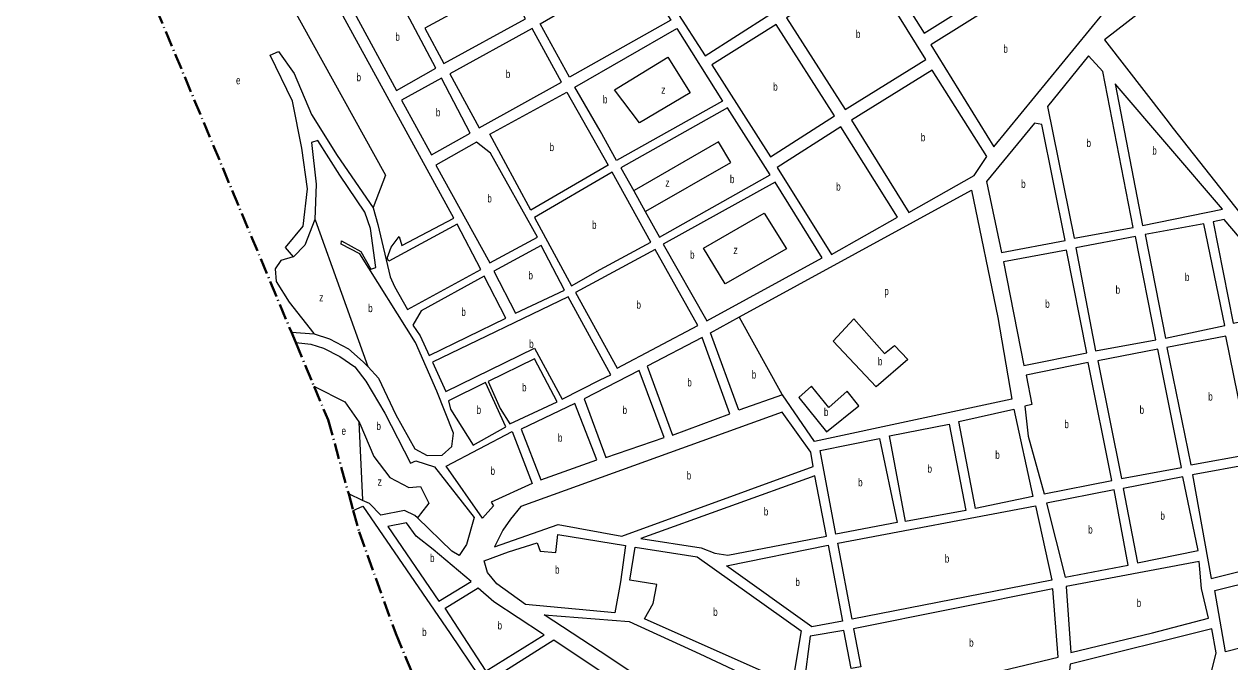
# Model space of a CAD drawing. Extents: x 639657 to 671642, y 222838 to 252123.
# Drawn here: x 641280 to 642787, y 245964 to 246761 of the extents above; entities that cross this region are included whole.
import ezdxf

# ---------------------------------------------------------------- set-up
doc = ezdxf.new("R2010")
doc.units = 0
doc.header["$LTSCALE"] = 4
doc.linetypes.add('DOT_DASHED', pattern=[7.7, 5, -1.2, 0.3, -1.2])
for name, color, linetype, lineweight in [('1', 7, 'Continuous', 13), ('21', 7, 'Continuous', 13), ('4', 7, 'DOT_DASHED', 40)]:
    doc.layers.add(name, color=color, linetype=linetype, lineweight=lineweight)
doc.layers.add('7', color=7, linetype='Continuous')

msp = doc.modelspace()

# ---------------------------------------------------------------- linework, layer by layer
at = {"layer": '1'}
msp.add_line((641614.514, 246376.116), (641643.04, 246373.95), dxfattribs=at)
for points in [[(641716.6, 246531.44), (641722.63, 246510.59), (641737.7, 246445.46), (641743.08, 246433.43), (641759.42, 246404.64), (641851.3, 246454.43), (641821.42, 246511.15), (641736.19, 246465.03), (641734.25, 246468.68), (641738.97, 246482.23), (641749.06, 246495.79), (641752.5, 246484.62), (641817.33, 246518.45), (641674.33, 246779.45), (641657.56, 246797.05), (641633.48, 246825.18), (641505.46, 247072.14), (641435.84, 247093.75)], [(642718.85, 246809.55), (642706.38, 246800.73), (642630.47, 246741.39), (642707.2, 246642.72), (642716.44, 246630.68)], [(641616.99, 246470.46), (641607.1, 246482.06), (641628.99, 246508.54), (641634.54, 246555.41), (641627.64, 246606.14), (641615.78, 246665.02), (641588.03, 246722.17), (641598.12, 246726.69), (641617.69, 246699.42), (641639.63, 246648.29), (641671.67, 246596.95), (641716.6, 246531.44)], [(642159.18, 246656.56), (642026.29, 246581.68), (642042.227, 246552.992), (642056.659, 246527.011)], [(642056.659, 246527.011), (642074.42, 246495.04), (642212.48, 246572.93), (642159.18, 246656.56)], [(642716.44, 246630.68), (642819.58, 246499.75), (642895.27, 246558.24), (642908.698, 246569.102)], [(641710.176, 246332.895), (641723.39, 246318.79), (641745.11, 246272.8), (641768.75, 246230.46), (641784.22, 246222.09), (641802.69, 246222.55), (641814.71, 246233.32), (641817.06, 246250.1), (641796.2, 246302.54), (641769.32, 246363.37), (641700.1, 246474.23), (641676.69, 246486.24), (641676.9, 246490.11), (641701.39, 246477.02), (641713.86, 246454.89), (641720.09, 246457.05), (641713.4, 246505.85), (641706.08, 246526.26), (641674.91, 246572.23), (641647.39, 246615.84), (641639.66, 246613.03), (641645.28, 246561.01), (641643.81, 246516.94)], [(642174.226, 246395.165), (642464.24, 246553.65), (642497.07, 246394.32), (642514.87, 246292.6), (642268.04, 246239.4), (642228.07, 246297.89), (642173.45, 246278.52)], [(641643.81, 246516.94), (641631.37, 246484.89), (641616.99, 246470.46)], [(642173.45, 246278.52), (642138.24, 246375.5), (642174.226, 246395.165)], [(641643.04, 246373.95), (641661.94, 246367.96), (641685.79, 246355.3), (641704.27, 246339.2), (641710.176, 246332.895)], [(641619.913, 246363.208), (641638.75, 246361.26), (641654.65, 246356.12), (641675.06, 246345.61), (641693.53, 246332.95), (641707.5, 246314.9), (641731.15, 246275.15), (641763.18, 246212.39), (641769.84, 246215.19), (641793.11, 246207.97), (641842.67, 246144.74), (641833.24, 246110.75), (641824.01, 246097.18), (641814.77, 246102.33), (641772.009, 246144.096)], [(641772.009, 246144.096), (641768.8, 246147.23), (641755.91, 246153.23), (641726.07, 246147.39), (641711.88, 246162), (641703.438, 246165.969), (641686.028, 246174.155)], [(641691.823, 246153.325), (641703.51, 246158.76), (641812.89, 245999.72), (641848.25, 245947.02), (641785.16, 245905.85), (641790.17, 245895.57)]]:
    msp.add_lwpolyline(points, dxfattribs=at)
for points in [[(642392.94, 246943.2), (642282, 246945.54), (642404.95, 246749.94), (642483.86, 246799.4)], [(642212.1, 246773.11), (642141.59, 246883.8), (642057.51, 246836.9), (642131.46, 246721.69)], [(642628.76, 246774.28), (642585.13, 246842.85), (642413.55, 246735.11), (642492.2, 246607.84)], [(642088.68, 246766.18), (641962.09, 246694.63), (641925.31, 246761.42), (641999.59, 246804.74), (642047.41, 246831.1)], [(642407.09, 246717.05), (642335.09, 246833.12), (642232.95, 246769.03), (642306.46, 246654.45)], [(641882.75, 246811.45), (641781.2, 246756.06), (641804.86, 246712.03), (641906.84, 246767.85)], [(641794.87, 246706.1), (641743.9, 246802.33), (641692.8, 246775.61), (641745.71, 246678.31)], [(641848.95, 246631.69), (641952, 246688.59), (641915.22, 246755.82), (641812.6, 246699.14)], [(642000.15, 246627.82), (641968.74, 246682.25), (642095.99, 246755.44), (642153.16, 246664.94), (642020.7, 246590.71)], [(642292.91, 246646.49), (642220.05, 246760.64), (642139.63, 246710.09), (642212.92, 246595.29)], [(642666.31, 246506.82), (642628.32, 246701.83), (642610.48, 246721.39), (642559.08, 246658.17), (642592.35, 246493.69)], [(641837.67, 246624.9), (641801.97, 246693.64), (641751.95, 246666.06), (641789.36, 246597.96)], [(642483.39, 246595.8), (642415.05, 246703.72), (642314.2, 246640.91), (642385.76, 246525.68), (642467.47, 246572.15)], [(641958.45, 246676.13), (642010.38, 246584.9), (641913.46, 246528.8), (641862.49, 246623.54)], [(642778.1, 246530.06), (642643.58, 246686.57), (642677.92, 246509.62)], [(642371.78, 246520.08), (642300.86, 246632.95), (642221.3, 246581.97), (642289.2, 246473.18)], [(642581.17, 246490.89), (642551.98, 246635.81), (642543.16, 246637.31), (642482.95, 246564.62), (642501.83, 246475.61)], [(641922.15, 246494.94), (641863.24, 246600), (641845.62, 246613.73), (641794.96, 246584.86), (641862.47, 246462.83)], [(641964.48, 246434.15), (642000.12, 246454.63), (642063.45, 246488.8), (642015.13, 246576.3), (641918.05, 246519.66)], [(642277.59, 246469.09), (642218.93, 246563.69), (642079.15, 246486.01), (642133.51, 246390.33)], [(642780.84, 246384.48), (642754.45, 246511.35), (642681.14, 246498.22), (642706.67, 246368.77)], [(642875.65, 246404.5), (642780.03, 246516.94), (642766.06, 246514.15), (642791.16, 246387.28)], [(642669.1, 246495.64), (642594.71, 246481.65), (642619.16, 246352.84), (642694.41, 246366.41)], [(641926.45, 246484.42), (641867.41, 246452.3), (641894.5, 246399.87), (641955.68, 246428.77)], [(641969.64, 246425.77), (642021.47, 246331.36), (642122.33, 246384.31), (642069.04, 246479.56)], [(642583.1, 246478.85), (642504.19, 246464), (642529.72, 246334.33), (642608.2, 246350.26)], [(641882.26, 246393.62), (641855.39, 246446.05), (641776.6, 246402.94), (641766.3, 246385.08), (641775.33, 246371.76), (641786.73, 246347.05)], [(641952.96, 246292.64), (642000.19, 246316.79), (642013.72, 246322.97), (641960.41, 246420.39), (641790.6, 246338.66), (641807.37, 246302.13), (641918.14, 246356.04)], [(642127.91, 246369.47), (642059.1, 246333.74), (642090.66, 246247.3), (642162.27, 246274.21)], [(642781.91, 246371.15), (642708.38, 246357.16), (642738.19, 246210.28), (642811.93, 246223.84)], [(642697.2, 246354.79), (642621.95, 246340.37), (642651.76, 246193.49), (642726.58, 246207.05)], [(641887.49, 246261.8), (641946.52, 246289.19), (641918.15, 246342.7), (641860.19, 246314.67), (641875.45, 246280.71)], [(642609.91, 246338.43), (642532.51, 246322.29), (642539.81, 246285.94), (642530.99, 246283.57), (642535.27, 246246.15), (642555.01, 246174.11), (642639.72, 246190.9)], [(641980.23, 246292.68), (642007.44, 246219.73), (642080.34, 246244.5), (642048.99, 246328.15)], [(641882.34, 246257.71), (641856.97, 246313.38), (641810.6, 246290.52), (641813.39, 246279.77), (641841.55, 246234.86)], [(641996.16, 246216.78), (641968.64, 246286.86), (641901.45, 246254.94), (641926.17, 246191.74)], [(641947.89, 246135.85), (642027.28, 246121.41), (642266.3, 246208.22), (642263.51, 246226.07), (642227.63, 246276.17), (641900.97, 246158.16), (641888.19, 246142.44), (641878.75, 246128.87), (641868.24, 246107.99)], [(642469.22, 246155.8), (642448.43, 246264.63), (642517.01, 246279.91), (642540.82, 246170.88)], [(642381.93, 246139.64), (642361.99, 246246.53), (642436.17, 246261.4), (642457.18, 246153.22)], [(641853.19, 246143.68), (641807.85, 246208.7), (641890.28, 246252.13), (641915.44, 246187), (641863.92, 246163.7), (641867.14, 246158.97)], [(642294.63, 246123.7), (642275.12, 246228.22), (642349.31, 246243.3), (642371.18, 246138.13)], [(642837, 246086.62), (642813.43, 246211.15), (642740.33, 246197.81), (642763.69, 246068.54)], [(642283.02, 246121.33), (642268.66, 246196.6), (642051.25, 246118.22), (642126.28, 246106.85), (642143.48, 246099.98), (642159.82, 246097.62)], [(642747.37, 246103.38), (642728.29, 246195.44), (642653.69, 246181.01), (642671.69, 246088.1)], [(642660.08, 246084.87), (642642.51, 246179.07), (642557.8, 246162.49), (642581.39, 246070.01)], [(642315, 246017.44), (642297.42, 246112.51), (642544.04, 246159.05), (642564.84, 246066.35)], [(641758.28, 246137.97), (641734.88, 246133.42), (641798.48, 246039.93), (641839.06, 246064.72), (641791.58, 246104.67), (641770.31, 246121.2)], [(642781.86, 245976.57), (642768.19, 246053.27), (642872.25, 246079.32), (642903, 246090.51), (642970.74, 246143.42), (643030.24, 246066.86), (642934.54, 245994.19), (642926.84, 245999.83), (642907.89, 246004.04), (642881.01, 246002.1)], [(642018.52, 246025.49), (641907.13, 246035.99), (641871.05, 246061.54), (641859.45, 246075.93), (641855.15, 246090.34), (641885.85, 246101.57), (641921.49, 246113.01), (641925.14, 246102.48), (641944.68, 246101), (641947.46, 246123.37), (642032.11, 246109.61), (642025.64, 246064.22)], [(642251.35, 246003), (642240.07, 245935.86), (642055.77, 246017.79), (642066.47, 246037.13), (642071, 246061.01), (642037.25, 246066.16), (642044.15, 246107.46), (642121.33, 246095.24)], [(642303.17, 246015.07), (642264.68, 246007.96), (642158.3, 246084.28), (642285.17, 246109.93)], [(642582.46, 246058.39), (642588.26, 245975.98), (642690.55, 246000.34), (642760.22, 246018.85), (642751.86, 246056.06), (642748.65, 246089.62)], [(641857.67, 245952.66), (641806.59, 246031.22), (641847.86, 246056.77), (641867.19, 246039.59), (641928.24, 245999.46), (641930.18, 245997.54)], [(642313.88, 245955.94), (642304.67, 246003.45), (642262.85, 245996.49), (642254.68, 245935.33), (642263.47, 245932.9), (642290.98, 245902.42), (642572.75, 245970.07), (642565.69, 246055.59), (642316.71, 246005.39), (642325.85, 245958.16)], [(642000.09, 245977.26), (641930.33, 246022.89), (642036.57, 246014.53), (642124.86, 245974.13), (642247.46, 245916.69), (642371.9, 245798.1), (642432.89, 245731.3), (642445.21, 245710.81), (642366.21, 245691.8), (642348.49, 245769.48), (642074.58, 245928.13)], [(642770.04, 245975.36), (642764.78, 246005.63), (642587.51, 245961.16), (642575.78, 245851.91), (642587.17, 245640.01), (642613.43, 245495.02), (642649.5, 245522.27), (642662.29, 245568.16), (642663.7, 245614.56), (642657.44, 245671.53), (642663.41, 245785.78), (642709.47, 245918.64), (642764.51, 245953.49)], [(642026.44, 245935.69), (641918.62, 245864.31), (641865.46, 245943.04), (641942.25, 245991.6)]]:
    msp.add_lwpolyline(points, close=True, dxfattribs=at)
at = {"layer": '21'}
for points in [[(641435.84, 247093.75), (641435.435, 247093.25), (641405.355, 247056.149), (641495.61, 247000.102), (641732.14, 246572.485), (641716.789, 246531.94), (641716.6, 246531.44)], [(642056.659, 246527.011), (642057.159, 246527.296), (642163.702, 246588.054), (642148.141, 246614.002), (642042.727, 246553.28), (642042.227, 246552.992)], [(641643.81, 246516.94), (641643.99, 246516.44), (641709.996, 246333.396), (641710.176, 246332.895)], [(641616.99, 246470.46), (641616.49, 246470.303), (641601.425, 246465.58), (641594.164, 246455.201), (641595.201, 246439.632), (641611.8, 246413.685), (641642.647, 246374.45), (641643.04, 246373.95)], [(642228.07, 246297.89), (642227.793, 246298.39), (642174.503, 246394.665), (642174.226, 246395.165)], [(641642.847, 246308.375), (641643.347, 246308.125), (641681.307, 246289.137), (641698.526, 246264.252)], [(641698.526, 246264.252), (641699.98, 246262.151), (641717.615, 246220.634), (641737.326, 246194.687), (641761.187, 246182.232), (641775.71, 246183.27), (641786.085, 246162.512), (641775.831, 246149.096), (641772.009, 246144.096)], [(641698.526, 246264.252), (641698.551, 246263.753), (641703.413, 246166.469), (641703.438, 246165.969)]]:
    msp.add_lwpolyline(points, dxfattribs=at)
for points in [[(642018.118, 246679.127), (642084.858, 246719.869), (642112.869, 246675.239), (642049.586, 246637.874)], [(642129.56, 246481.341), (642205.198, 246524.742), (642233.208, 246480.112), (642156.44, 246436.52)], [(642291.589, 246364.93), (642317.239, 246392.926), (642355.623, 246349.334), (642368.072, 246359.713), (642384.671, 246342.069), (642345.249, 246307.818)], [(642248.481, 246294.439), (642283.005, 246251.771), (642323.464, 246283.946), (642308.94, 246302.628), (642286.117, 246281.87), (642264.331, 246308.856)]]:
    msp.add_lwpolyline(points, close=True, dxfattribs=at)
at = {"layer": '4'}
for points in [[(641280.444, 247149.734), (641303.72, 247093.59), (641336.22, 247032.82), (641421.68, 246837.16), (641614.514, 246376.116), (641619.913, 246363.208), (641642.847, 246308.375)], [(641642.847, 246308.375), (641660.29, 246266.67), (641686.028, 246174.155), (641691.823, 246153.325)], [(641691.823, 246153.325), (641699.23, 246126.7), (641744.82, 245999.63), (641775.1, 245927.21)]]:
    msp.add_lwpolyline(points, dxfattribs=at)

# ---------------------------------------------------------------- texts
at = {"layer": '7'}
for s, width, p in [('b', 0.75, (641744.367, 246740.32)), ('b', 0.75, (642319.826, 246743.785)), ('b', 0.75, (642504.097, 246725.345)), ('e', 0.75, (641545.288, 246685.912)), ('b', 0.75, (641695.831, 246689.767)), ('b', 0.75, (641882.338, 246693.755)), ('z', 0.8, (642076.56, 246674.199)), ('b', 0.75, (642216.48, 246677.965)), ('b', 0.75, (642003.685, 246662.045)), ('b', 0.75, (641794.948, 246645.8)), ('b', 0.75, (642400.949, 246614.7)), ('b', 0.75, (642608.005, 246607.54)), ('b', 0.75, (641937.105, 246602.465)), ('b', 0.75, (642690.187, 246598.095)), ('b', 0.75, (642162.409, 246562.406)), ('z', 0.8, (642081.747, 246557.954)), ('b', 0.75, (642295.198, 246553.065)), ('b', 0.75, (642526.322, 246556.46)), ('b', 0.75, (641859.289, 246538.28)), ('b', 0.75, (641990.134, 246505.225)), ('z', 0.8, (642166.815, 246473.884)), ('b', 0.75, (642112.614, 246467.957)), ('b', 0.75, (641910.656, 246442.145)), ('b', 0.75, (642730.945, 246440.06)), ('b', 0.75, (642644.346, 246424.24)), ('z', 0.8, (641649.146, 246414.723)), ('p', 0.75, (642355.339, 246422.473)), ('b', 0.75, (641710.354, 246401.229)), ('b', 0.75, (641826.837, 246396.55)), ('b', 0.75, (642045.644, 246405.46)), ('b', 0.75, (642556.349, 246406.59)), ('b', 0.75, (641911.53, 246356.515)), ('b', 0.75, (642347.324, 246334.803)), ('b', 0.75, (642189.638, 246318.197)), ('b', 0.75, (642109.15, 246308.385)), ('b', 0.75, (641902.683, 246302.25)), ('b', 0.75, (642760.084, 246290.715)), ('b', 0.75, (641845.897, 246274.12)), ('b', 0.75, (642028.263, 246273.94)), ('b', 0.75, (642674.315, 246274.14)), ('b', 0.75, (642279.892, 246271.491)), ('e', 0.75, (641677.039, 246247.916)), ('b', 0.75, (641720.728, 246253.847)), ('b', 0.75, (642580.312, 246256.27)), ('b', 0.75, (641947.442, 246239.3)), ('b', 0.75, (642493.964, 246217.855)), ('b', 0.75, (641863.302, 246197.905)), ('b', 0.75, (642409.283, 246200.52)), ('b', 0.75, (642108.362, 246192.08)), ('b', 0.75, (642322.606, 246183.5)), ('z', 0.8, (641722.214, 246184.412)), ('b', 0.75, (642204.743, 246147.11)), ('b', 0.75, (642700.353, 246141.77)), ('b', 0.75, (642610.081, 246124.54)), ('b', 0.75, (641787.698, 246088.95)), ('b', 0.75, (642430.917, 246088.245)), ('b', 0.75, (641943.877, 246074.43)), ('b', 0.75, (642244.229, 246058.945)), ('b', 0.75, (642670.673, 246032.8)), ('b', 0.75, (642141.479, 246021.66)), ('b', 0.75, (641872.035, 246004.715)), ('b', 0.75, (641777.785, 245996.447)), ('b', 0.75, (642461.322, 245983.156))]:
    msp.add_text(s, height=10, dxfattribs=dict(at, width=width)).set_placement(p)

doc.saveas('drawing.dxf')
